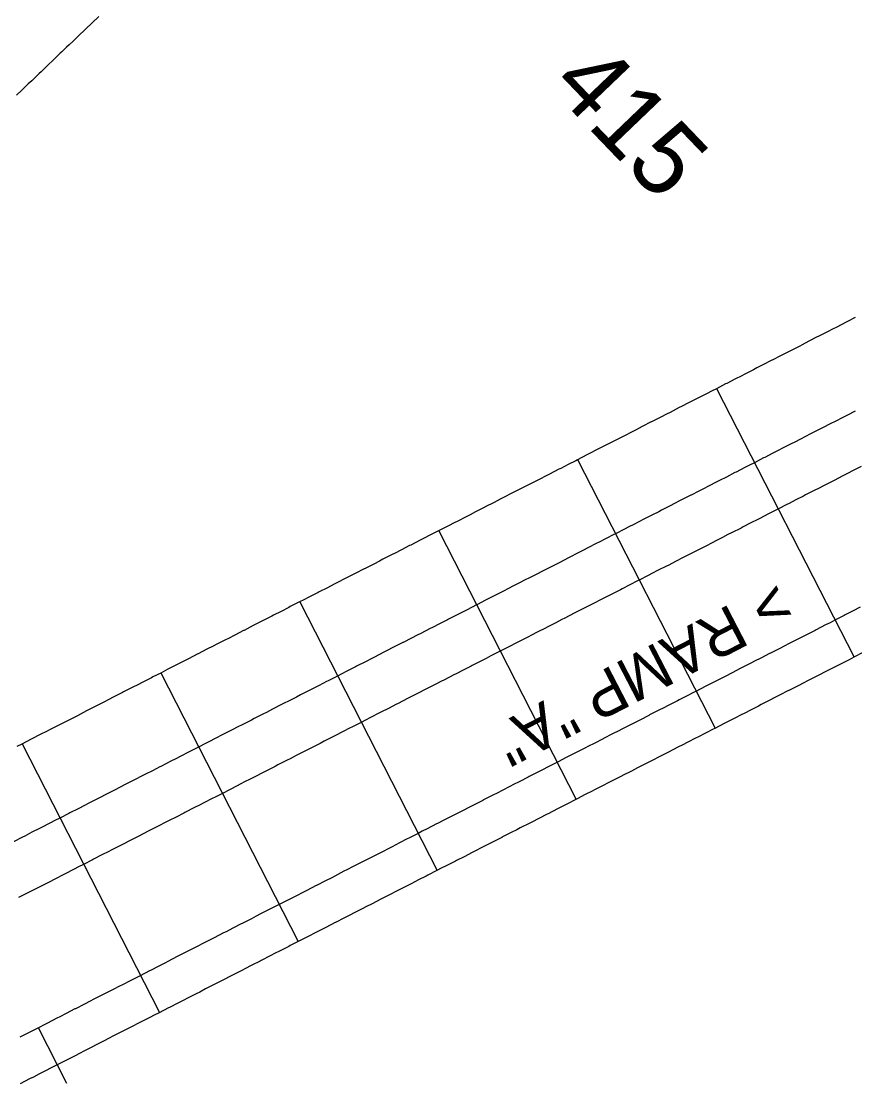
# Model space of a CAD drawing. Extents: x 2145147 to 2158018, y 137519 to 148068.
# Drawn here: x 2149996.5 to 2150076.6, y 143335.3 to 143437.4 of the extents above; entities that cross this region are included whole.
import ezdxf

# ---------------------------------------------------------------- set-up
doc = ezdxf.new("R2010")
doc.units = 0
for name, color, linetype in [('PR_Align_Ramp_A', 7, 'Continuous'), ('PR_Align_Ramp_A_Label', 7, 'Continuous'), ('PR_Align_Ramp_F_Sta', 7, 'Continuous'), ('PR_Joint_Contraction', 7, 'Continuous'), ('PR_Joint_Long', 7, 'Continuous'), ('PR_Road_Concrete', 7, 'Continuous')]:
    doc.layers.add(name, color=color, linetype=linetype)

msp = doc.modelspace()

# ---------------------------------------------------------------- linework, layer by layer
at = {"layer": 'PR_Align_Ramp_A'}
msp.add_lwpolyline([(2150000.9, 143335.36), (2149998.17, 143340.71)], dxfattribs=at)
at = {"layer": 'PR_Joint_Contraction'}
for p, q in [((2150063.37, 143402.14), (2150076.58, 143376.33)), ((2150050.01, 143395.31), (2150063.22, 143369.49)), ((2150036.66, 143388.48), (2150049.87, 143362.66)), ((2150023.31, 143381.65), (2150036.52, 143355.83)), ((2150009.95, 143374.82), (2150023.16, 143349)), ((2149996.6, 143367.98), (2150009.81, 143342.17))]:
    msp.add_line(p, q, dxfattribs=at)
at = {"layer": 'PR_Joint_Long'}
for points in [[(2150076.69, 143399.97), (2150075.89, 143399.56), (2150075.26, 143399.24), (2150075.01, 143399.11), (2150074.1, 143398.65), (2150073.8, 143398.49), (2150073.22, 143398.2), (2150072.41, 143397.78), (2150072.4, 143397.78), (2150071.45, 143397.29), (2150070.89, 143397), (2150070.54, 143396.83), (2150069.65, 143396.37), (2150069.43, 143396.26), (2150068.77, 143395.92), (2150068, 143395.53), (2150067.89, 143395.47), (2150067, 143395.01), (2150066.54, 143394.78), (2150066.09, 143394.55), (2150065.25, 143394.12), (2150065.13, 143394.06), (2150064.31, 143393.64), (2150063.66, 143393.31), (2150063.45, 143393.2), (2150062.53, 143392.73), (2150062.18, 143392.55), (2150061.65, 143392.28), (2150060.93, 143391.91), (2150060.9, 143391.9), (2150059.87, 143391.37), (2150059.27, 143391.06), (2150058.97, 143390.91), (2150058.08, 143390.45), (2150057.81, 143390.31), (2150057.2, 143390), (2150056.44, 143389.61), (2150056.37, 143389.58), (2150055.42, 143389.09), (2150054.92, 143388.84), (2150054.52, 143388.63), (2150053.65, 143388.18), (2150053.49, 143388.1), (2150052.74, 143387.72), (2150052.01, 143387.35), (2150051.85, 143387.27), (2150050.98, 143386.82), (2150050.57, 143386.61), (2150050.07, 143386.35), (2150049.21, 143385.91), (2150049.14, 143385.88), (2150048.29, 143385.44), (2150047.66, 143385.12), (2150047.41, 143384.99), (2150046.51, 143384.53), (2150046.21, 143384.38), (2150045.63, 143384.08), (2150044.72, 143383.62), (2150044.69, 143383.6), (2150043.85, 143383.17), (2150043.31, 143382.9), (2150042.95, 143382.71), (2150042.06, 143382.25), (2150041.86, 143382.15), (2150041.17, 143381.8), (2150040.4, 143381.4), (2150040.28, 143381.35), (2150039.4, 143380.89), (2150038.94, 143380.66), (2150038.49, 143380.43), (2150037.6, 143379.97), (2150037.49, 143379.92), (2150036.72, 143379.52), (2150036.06, 143379.18), (2150035.85, 143379.08), (2150034.94, 143378.61), (2150034.59, 143378.43), (2150034.05, 143378.15), (2150033.23, 143377.74), (2150033.21, 143377.73), (2150032.26, 143377.24), (2150031.7, 143376.96), (2150031.39, 143376.8), (2150030.48, 143376.33), (2150030.24, 143376.21), (2150029.61, 143375.88), (2150028.76, 143375.45), (2150028.67, 143375.41), (2150027.82, 143374.97), (2150027.33, 143374.72), (2150026.92, 143374.51), (2150026.03, 143374.05), (2150025.88, 143373.98), (2150025.15, 143373.6), (2150024.45, 143373.25), (2150024.28, 143373.16), (2150023.37, 143372.69), (2150022.98, 143372.49), (2150022.48, 143372.24), (2150021.55, 143371.76), (2150021.49, 143371.73), (2150020.69, 143371.32), (2150020.09, 143371.02), (2150019.82, 143370.88), (2150018.93, 143370.42), (2150018.65, 143370.28), (2150018.02, 143369.96), (2150017.1, 143369.49), (2150017.06, 143369.47), (2150016.24, 143369.05), (2150015.72, 143368.78), (2150015.36, 143368.59), (2150014.44, 143368.13), (2150014.25, 143368.03), (2150013.58, 143367.68), (2150012.81, 143367.29), (2150012.66, 143367.22), (2150011.8, 143366.77), (2150011.38, 143366.56), (2150010.9, 143366.32), (2150009.96, 143365.83), (2150009.86, 143365.78), (2150009.13, 143365.41), (2150008.47, 143365.07), (2150008.22, 143364.95), (2150007.35, 143364.5), (2150007.02, 143364.33), (2150006.45, 143364.04), (2150005.56, 143363.58), (2150004.67, 143363.12), (2150004.11, 143362.84), (2150003.79, 143362.68), (2150002.9, 143362.22), (2150002.66, 143362.1), (2150002, 143361.76), (2150001.19, 143361.35), (2150001.09, 143361.29), (2150000.22, 143360.85), (2149999.76, 143360.61), (2149999.34, 143360.4), (2149998.4, 143359.92), (2149998.27, 143359.85), (2149997.56, 143359.49), (2149996.87, 143359.13), (2149996.66, 143359.03), (2149995.77, 143358.57)], [(2150077.28, 143394.66), (2150076.38, 143394.2), (2150076.07, 143394.04), (2150075.5, 143393.75), (2150074.67, 143393.32), (2150074.66, 143393.32), (2150073.72, 143392.84), (2150073.16, 143392.55), (2150072.82, 143392.38), (2150071.93, 143391.92), (2150071.71, 143391.81), (2150071.05, 143391.47), (2150070.28, 143391.07), (2150070.17, 143391.02), (2150069.27, 143390.56), (2150068.82, 143390.33), (2150068.37, 143390.1), (2150067.52, 143389.66), (2150067.39, 143389.6), (2150066.59, 143389.19), (2150065.93, 143388.85), (2150065.72, 143388.74), (2150064.81, 143388.28), (2150064.46, 143388.1), (2150063.93, 143387.83), (2150063.16, 143387.43), (2150063.13, 143387.42), (2150062.14, 143386.91), (2150061.55, 143386.61), (2150061.25, 143386.46), (2150060.36, 143386), (2150060.09, 143385.87), (2150059.47, 143385.55), (2150058.7, 143385.15), (2150058.63, 143385.12), (2150057.7, 143384.64), (2150057.2, 143384.39), (2150056.8, 143384.18), (2150055.92, 143383.73), (2150055.76, 143383.65), (2150055.02, 143383.27), (2150054.29, 143382.9), (2150054.13, 143382.81), (2150053.25, 143382.36), (2150052.85, 143382.16), (2150052.35, 143381.9), (2150051.48, 143381.46), (2150051.41, 143381.42), (2150050.57, 143380.99), (2150049.94, 143380.67), (2150049.68, 143380.54), (2150048.79, 143380.08), (2150048.48, 143379.93), (2150047.91, 143379.63), (2150047.01, 143379.17), (2150046.98, 143379.16), (2150046.12, 143378.72), (2150045.59, 143378.44), (2150045.23, 143378.26), (2150044.34, 143377.8), (2150044.13, 143377.7), (2150043.45, 143377.35), (2150042.68, 143376.95), (2150042.56, 143376.89), (2150041.67, 143376.44), (2150041.22, 143376.21), (2150040.77, 143375.98), (2150039.88, 143375.52), (2150039.77, 143375.47), (2150039, 143375.07), (2150038.33, 143374.73), (2150038.12, 143374.62), (2150037.22, 143374.16), (2150036.87, 143373.98), (2150036.32, 143373.7), (2150035.49, 143373.28), (2150035.47, 143373.27), (2150034.54, 143372.79), (2150033.98, 143372.5), (2150033.66, 143372.34), (2150032.76, 143371.88), (2150032.52, 143371.76), (2150031.88, 143371.43), (2150031.04, 143371), (2150030.96, 143370.96), (2150030.1, 143370.52), (2150029.61, 143370.27), (2150029.2, 143370.06), (2150028.31, 143369.6), (2150028.16, 143369.53), (2150027.42, 143369.15), (2150026.73, 143368.79), (2150026.55, 143368.7), (2150025.65, 143368.24), (2150025.26, 143368.04), (2150024.75, 143367.78), (2150023.84, 143367.32), (2150023.78, 143367.29), (2150022.97, 143366.87), (2150022.37, 143366.56), (2150022.09, 143366.42), (2150021.2, 143365.97), (2150020.92, 143365.82), (2150020.3, 143365.51), (2150019.4, 143365.05), (2150019.36, 143365.03), (2150018.52, 143364.6), (2150018, 143364.33), (2150017.63, 143364.14), (2150016.73, 143363.68), (2150016.53, 143363.58), (2150015.86, 143363.23), (2150015.09, 143362.84), (2150014.95, 143362.77), (2150014.08, 143362.32), (2150013.66, 143362.11), (2150013.18, 143361.86), (2150012.25, 143361.39), (2150012.16, 143361.34), (2150011.41, 143360.96), (2150010.74, 143360.62), (2150010.5, 143360.5), (2150009.62, 143360.04), (2150009.3, 143359.88), (2150008.73, 143359.59), (2150007.84, 143359.13), (2150006.94, 143358.67), (2150006.39, 143358.39), (2150006.06, 143358.22), (2150005.17, 143357.77), (2150004.94, 143357.65), (2150004.28, 143357.31), (2150003.47, 143356.9), (2150003.37, 143356.85), (2150002.5, 143356.4), (2150002.04, 143356.16), (2150001.61, 143355.95), (2150000.69, 143355.47), (2150000.55, 143355.4), (2149999.83, 143355.03), (2149999.14, 143354.68), (2149998.94, 143354.58), (2149998.05, 143354.12), (2149997.68, 143353.93), (2149997.15, 143353.66), (2149996.26, 143353.21)], [(2150077.18, 143381.13), (2150076.51, 143380.79), (2150075.73, 143380.39), (2150075.62, 143380.33), (2150074.73, 143379.88), (2150074.28, 143379.64), (2150073.84, 143379.42), (2150072.95, 143378.96), (2150072.83, 143378.9), (2150072.06, 143378.51), (2150071.38, 143378.16), (2150071.17, 143378.05), (2150070.28, 143377.6), (2150069.92, 143377.41), (2150069.39, 143377.14), (2150068.5, 143376.69), (2150068.47, 143376.67), (2150067.61, 143376.23), (2150067.02, 143375.93), (2150066.72, 143375.78), (2150065.83, 143375.32), (2150065.57, 143375.19), (2150064.94, 143374.86), (2150064.12, 143374.44), (2150064.05, 143374.41), (2150063.16, 143373.95), (2150062.67, 143373.7), (2150062.27, 143373.5), (2150061.38, 143373.04), (2150061.21, 143372.96), (2150060.49, 143372.59), (2150059.76, 143372.22), (2150059.6, 143372.13), (2150058.71, 143371.68), (2150058.31, 143371.47), (2150057.82, 143371.22), (2150056.93, 143370.77), (2150056.86, 143370.73), (2150056.04, 143370.31), (2150055.41, 143369.99), (2150055.15, 143369.85), (2150054.26, 143369.4), (2150053.96, 143369.24), (2150053.37, 143368.94), (2150052.5, 143368.5), (2150052.48, 143368.49), (2150051.59, 143368.03), (2150051.05, 143367.76), (2150050.7, 143367.58), (2150049.8, 143367.12), (2150049.6, 143367.02), (2150048.92, 143366.67), (2150048.15, 143366.27), (2150048.02, 143366.21), (2150047.13, 143365.76), (2150046.7, 143365.53), (2150046.24, 143365.3), (2150045.35, 143364.85), (2150045.24, 143364.79), (2150044.46, 143364.39), (2150043.79, 143364.05), (2150043.57, 143363.93), (2150042.68, 143363.48), (2150042.34, 143363.3), (2150041.79, 143363.02), (2150040.9, 143362.57), (2150040.89, 143362.56), (2150040.01, 143362.11), (2150039.44, 143361.82), (2150039.12, 143361.66), (2150038.23, 143361.2), (2150037.99, 143361.07), (2150037.34, 143360.75), (2150036.53, 143360.33), (2150036.45, 143360.29), (2150035.56, 143359.83), (2150035.08, 143359.59), (2150034.67, 143359.38), (2150033.78, 143358.92), (2150033.63, 143358.85), (2150032.89, 143358.47), (2150032.18, 143358.1), (2150032, 143358.01), (2150031.11, 143357.56), (2150030.73, 143357.36), (2150030.22, 143357.1), (2150029.33, 143356.65), (2150029.27, 143356.62), (2150028.44, 143356.19), (2150027.82, 143355.88), (2150027.55, 143355.74), (2150026.66, 143355.28), (2150026.37, 143355.13), (2150025.77, 143354.82), (2150024.92, 143354.39), (2150024.88, 143354.37), (2150023.99, 143353.91), (2150023.47, 143353.65), (2150023.1, 143353.46), (2150022.21, 143353), (2150022.02, 143352.9), (2150021.32, 143352.55), (2150020.56, 143352.16), (2150020.43, 143352.09), (2150019.54, 143351.64), (2150019.11, 143351.42), (2150018.65, 143351.18), (2150017.76, 143350.73), (2150017.66, 143350.68), (2150016.87, 143350.27), (2150016.21, 143349.93), (2150015.98, 143349.82), (2150015.08, 143349.36), (2150014.76, 143349.19), (2150014.19, 143348.9), (2150013.31, 143348.45), (2150013.3, 143348.45), (2150012.42, 143347.99), (2150011.85, 143347.71), (2150011.52, 143347.54), (2150010.63, 143347.08), (2150010.4, 143346.96), (2150009.74, 143346.63), (2150008.95, 143346.22), (2150008.85, 143346.17), (2150007.96, 143345.71), (2150007.5, 143345.48), (2150007.07, 143345.26), (2150006.18, 143344.8), (2150006.05, 143344.73), (2150005.29, 143344.35), (2150004.6, 143343.99), (2150004.4, 143343.89), (2150003.51, 143343.44), (2150003.14, 143343.25), (2150002.62, 143342.98), (2150001.73, 143342.53), (2150001.69, 143342.51), (2150000.84, 143342.07), (2150000.24, 143341.77), (2149999.95, 143341.62), (2149999.06, 143341.16), (2149998.79, 143341.02), (2149998.17, 143340.7), (2149997.34, 143340.28), (2149997.28, 143340.25), (2149996.39, 143339.79)]]:
    msp.add_lwpolyline(points, dxfattribs=at)
at = {"layer": 'PR_Road_Concrete'}
for points in [[(2150003.97, 143437.9), (2150003.35, 143437.31), (2150003.3, 143437.27), (2150002.74, 143436.72), (2150002.58, 143436.57), (2150002.12, 143436.14), (2150001.86, 143435.88), (2150001.51, 143435.55), (2150001.14, 143435.19), (2150000.89, 143434.96), (2150000.42, 143434.5), (2150000.28, 143434.37), (2149999.69, 143433.81), (2149999.66, 143433.78), (2149999.05, 143433.19), (2149998.97, 143433.11), (2149998.43, 143432.6), (2149998.25, 143432.42), (2149997.82, 143432.01), (2149997.53, 143431.73), (2149997.2, 143431.42), (2149996.81, 143431.04), (2149996.59, 143430.83), (2149996.08, 143430.35)], [(2150076.7, 143408.96), (2150075.96, 143408.58), (2150075.81, 143408.51), (2150074.92, 143408.05), (2150074.51, 143407.84), (2150074.03, 143407.6), (2150073.14, 143407.14), (2150073.05, 143407.1), (2150072.25, 143406.69), (2150071.6, 143406.36), (2150071.36, 143406.23), (2150070.47, 143405.77), (2150070.15, 143405.61), (2150069.58, 143405.32), (2150068.7, 143404.87), (2150068.69, 143404.86), (2150067.8, 143404.41), (2150067.25, 143404.13), (2150066.91, 143403.95), (2150066.02, 143403.5), (2150065.8, 143403.38), (2150065.13, 143403.04), (2150064.34, 143402.64), (2150064.24, 143402.59), (2150063.35, 143402.13), (2150062.89, 143401.9), (2150062.46, 143401.68), (2150061.56, 143401.22), (2150061.44, 143401.16), (2150060.67, 143400.77), (2150059.99, 143400.41), (2150059.78, 143400.31), (2150058.89, 143399.85), (2150058.54, 143399.67), (2150058, 143399.4), (2150057.11, 143398.94), (2150057.09, 143398.93), (2150056.22, 143398.49), (2150055.63, 143398.19), (2150055.33, 143398.03), (2150054.44, 143397.58), (2150054.18, 143397.44), (2150053.55, 143397.12), (2150052.73, 143396.7), (2150052.66, 143396.67), (2150051.77, 143396.21), (2150051.28, 143395.96), (2150050.88, 143395.76), (2150049.99, 143395.3), (2150049.83, 143395.21), (2150049.1, 143394.84), (2150048.38, 143394.47), (2150048.21, 143394.39), (2150047.32, 143393.93), (2150046.92, 143393.73), (2150046.43, 143393.48), (2150045.54, 143393.02), (2150045.47, 143392.99), (2150044.65, 143392.57), (2150044.02, 143392.24), (2150043.76, 143392.11), (2150042.87, 143391.66), (2150042.57, 143391.5), (2150041.98, 143391.2), (2150041.12, 143390.76), (2150041.09, 143390.74), (2150040.2, 143390.29), (2150039.67, 143390.02), (2150039.31, 143389.83), (2150038.42, 143389.38), (2150038.21, 143389.27), (2150037.53, 143388.92), (2150036.76, 143388.53), (2150036.64, 143388.47), (2150035.75, 143388.01), (2150035.31, 143387.79), (2150034.86, 143387.56), (2150033.97, 143387.1), (2150033.86, 143387.05), (2150033.08, 143386.65), (2150032.41, 143386.3), (2150032.19, 143386.19), (2150031.3, 143385.73), (2150030.95, 143385.56), (2150030.41, 143385.28), (2150029.52, 143384.82), (2150029.5, 143384.82), (2150028.63, 143384.37), (2150028.05, 143384.07), (2150027.74, 143383.91), (2150026.85, 143383.46), (2150026.6, 143383.33), (2150025.96, 143383), (2150025.15, 143382.59), (2150025.06, 143382.55), (2150024.17, 143382.09), (2150023.7, 143381.85), (2150023.28, 143381.64), (2150022.39, 143381.18), (2150022.24, 143381.1), (2150021.5, 143380.72), (2150020.79, 143380.36), (2150020.61, 143380.27), (2150019.72, 143379.81), (2150019.34, 143379.62), (2150018.83, 143379.36), (2150017.94, 143378.9), (2150017.89, 143378.88), (2150017.05, 143378.45), (2150016.44, 143378.13), (2150016.16, 143377.99), (2150015.27, 143377.54), (2150014.98, 143377.39), (2150014.38, 143377.08), (2150013.53, 143376.65), (2150013.49, 143376.63), (2150012.6, 143376.17), (2150012.08, 143375.9), (2150011.71, 143375.71), (2150010.82, 143375.26), (2150010.63, 143375.16), (2150009.93, 143374.8), (2150009.18, 143374.42), (2150009.04, 143374.35), (2150008.15, 143373.89), (2150007.73, 143373.68), (2150007.26, 143373.44), (2150006.37, 143372.98), (2150006.27, 143372.93), (2150005.48, 143372.53), (2150004.82, 143372.19), (2150004.59, 143372.07), (2150003.7, 143371.61), (2150003.37, 143371.45), (2150002.81, 143371.16), (2150001.92, 143370.7), (2150001.92, 143370.7), (2150001.03, 143370.25), (2150000.47, 143369.96), (2150000.14, 143369.79), (2149999.25, 143369.34), (2149999.02, 143369.22), (2149998.36, 143368.88), (2149997.56, 143368.48), (2149997.47, 143368.43), (2149996.58, 143367.97), (2149996.11, 143367.73)], [(2150077.44, 143376.77), (2150076.55, 143376.31), (2150076.1, 143376.08), (2150075.66, 143375.86), (2150074.77, 143375.4), (2150074.65, 143375.34), (2150073.88, 143374.95), (2150073.2, 143374.6), (2150072.99, 143374.49), (2150072.1, 143374.04), (2150071.75, 143373.85), (2150071.21, 143373.58), (2150070.32, 143373.13), (2150070.29, 143373.11), (2150069.43, 143372.67), (2150068.84, 143372.37), (2150068.54, 143372.21), (2150067.65, 143371.76), (2150067.39, 143371.63), (2150066.76, 143371.3), (2150065.94, 143370.88), (2150065.87, 143370.85), (2150064.98, 143370.39), (2150064.49, 143370.14), (2150064.09, 143369.94), (2150063.2, 143369.48), (2150063.03, 143369.4), (2150062.31, 143369.03), (2150061.58, 143368.65), (2150061.42, 143368.57), (2150060.53, 143368.12), (2150060.13, 143367.91), (2150059.64, 143367.66), (2150058.75, 143367.2), (2150058.68, 143367.17), (2150057.86, 143366.75), (2150057.23, 143366.43), (2150056.97, 143366.29), (2150056.08, 143365.84), (2150055.78, 143365.68), (2150055.19, 143365.38), (2150054.32, 143364.94), (2150054.3, 143364.93), (2150053.41, 143364.47), (2150052.87, 143364.2), (2150052.52, 143364.02), (2150051.63, 143363.56), (2150051.42, 143363.46), (2150050.74, 143363.11), (2150049.97, 143362.71), (2150049.85, 143362.65), (2150048.96, 143362.19), (2150048.52, 143361.97), (2150048.07, 143361.74), (2150047.18, 143361.28), (2150047.07, 143361.23), (2150046.29, 143360.83), (2150045.62, 143360.48), (2150045.4, 143360.37), (2150044.5, 143359.92), (2150044.16, 143359.74), (2150043.62, 143359.46), (2150042.72, 143359.01), (2150042.71, 143359), (2150041.83, 143358.55), (2150041.26, 143358.26), (2150040.94, 143358.1), (2150040.05, 143357.64), (2150039.81, 143357.51), (2150039.16, 143357.18), (2150038.36, 143356.77), (2150038.27, 143356.73), (2150037.38, 143356.27), (2150036.9, 143356.03), (2150036.49, 143355.82), (2150035.6, 143355.36), (2150035.45, 143355.29), (2150034.71, 143354.91), (2150034, 143354.54), (2150033.82, 143354.45), (2150032.93, 143354), (2150032.55, 143353.8), (2150032.04, 143353.54), (2150031.15, 143353.09), (2150031.1, 143353.06), (2150030.26, 143352.63), (2150029.65, 143352.32), (2150029.37, 143352.17), (2150028.48, 143351.72), (2150028.19, 143351.57), (2150027.59, 143351.26), (2150026.74, 143350.83), (2150026.7, 143350.81), (2150025.81, 143350.35), (2150025.29, 143350.09), (2150024.92, 143349.9), (2150024.03, 143349.44), (2150023.84, 143349.34), (2150023.14, 143348.99), (2150022.39, 143348.6), (2150022.25, 143348.53), (2150021.36, 143348.07), (2150020.94, 143347.86), (2150020.47, 143347.62), (2150019.58, 143347.16), (2150019.48, 143347.12), (2150018.69, 143346.71), (2150018.03, 143346.37), (2150017.8, 143346.25), (2150016.91, 143345.8), (2150016.58, 143345.63), (2150016.02, 143345.34), (2150015.13, 143344.89), (2150015.13, 143344.89), (2150014.24, 143344.43), (2150013.68, 143344.14), (2150013.35, 143343.98), (2150012.46, 143343.52), (2150012.22, 143343.4), (2150011.57, 143343.07), (2150010.77, 143342.66), (2150010.67, 143342.61), (2150009.78, 143342.15), (2150009.32, 143341.92), (2150008.9, 143341.7), (2150008, 143341.24), (2150007.87, 143341.17), (2150007.11, 143340.79), (2150006.42, 143340.43), (2150006.22, 143340.33), (2150005.33, 143339.88), (2150004.97, 143339.69), (2150004.44, 143339.42), (2150003.55, 143338.97), (2150003.51, 143338.95), (2150002.66, 143338.51), (2150002.06, 143338.2), (2150001.77, 143338.05), (2150000.88, 143337.6), (2150000.61, 143337.46), (2149999.99, 143337.14), (2149999.16, 143336.72), (2149999.1, 143336.69), (2149998.21, 143336.23), (2149997.71, 143335.97), (2149997.32, 143335.78), (2149996.43, 143335.32)]]:
    msp.add_lwpolyline(points, dxfattribs=at)

# ---------------------------------------------------------------- texts
at = {"layer": 'PR_Align_Ramp_A_Label'}
msp.add_text('> RAMP "A"', height=4.3, rotation=207.3641, dxfattribs=at).set_placement((2150069.14, 143383.78))
at = {"layer": 'PR_Align_Ramp_F_Sta'}
msp.add_text('415', height=7, rotation=313.7809, dxfattribs=at).set_placement((2150047.21, 143431.16))

doc.saveas('drawing.dxf')
